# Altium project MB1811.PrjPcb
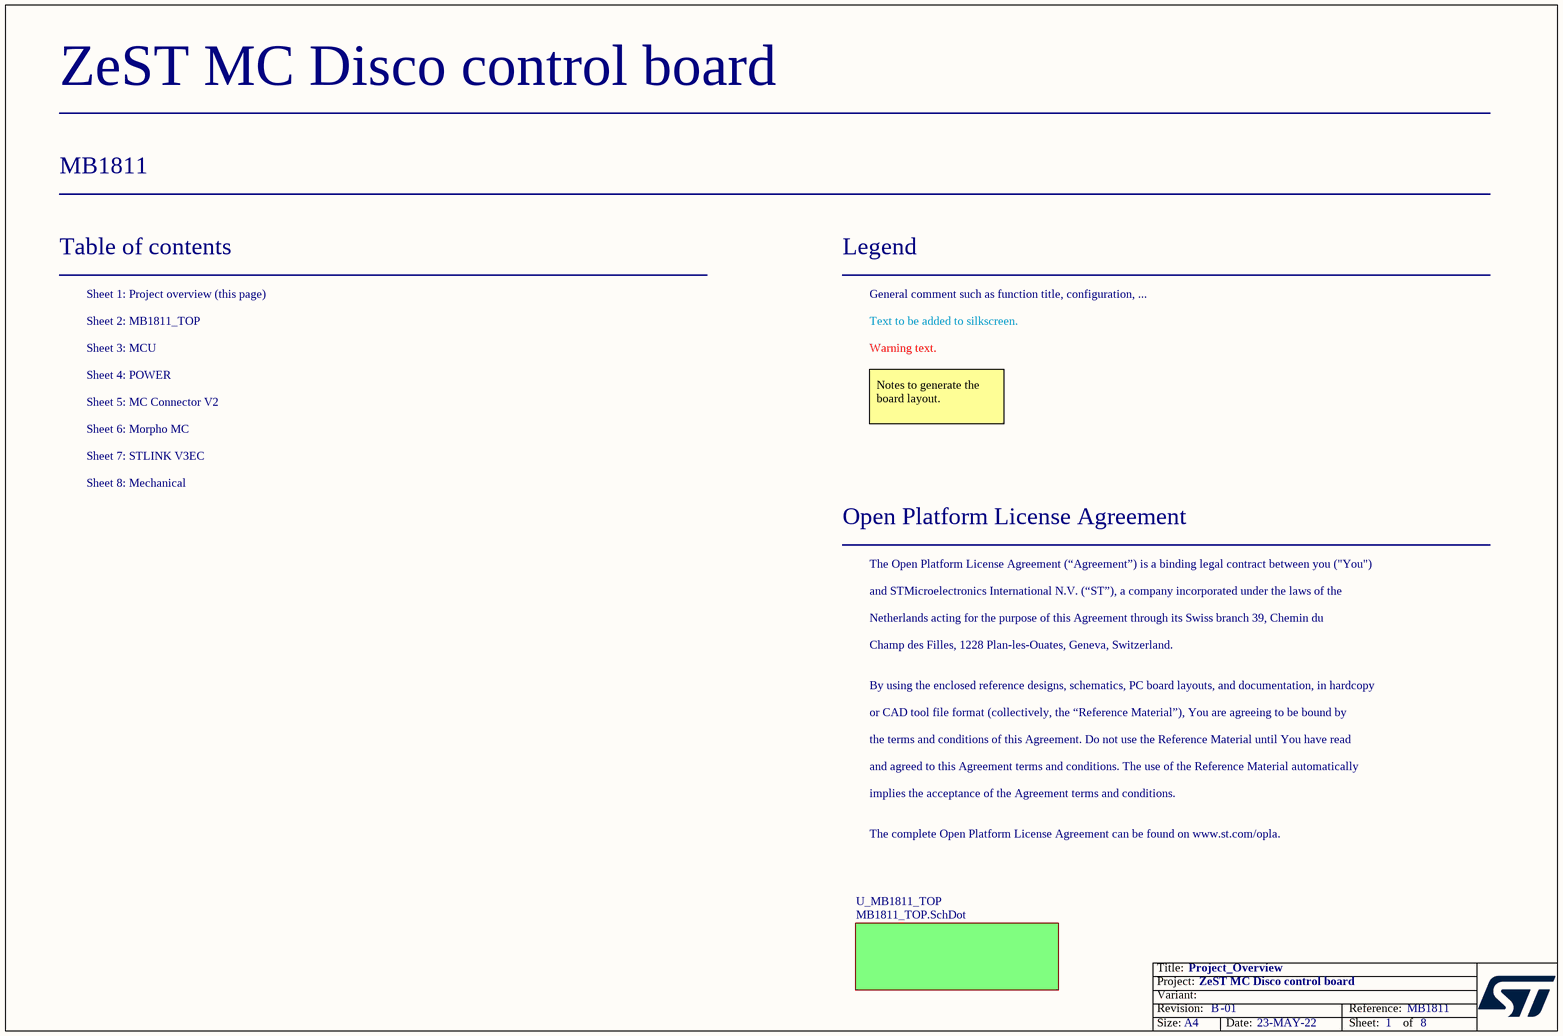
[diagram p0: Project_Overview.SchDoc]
Board_Assembly_Revision: 01; Board_Document_Date: 23-MAY-22; Board_Name: ZeST MC Disco control board; Board_PCB_Revision: B; Board_Reference: MB1811
2 sheets, 89 parts. Net scope: flat (ports and power ports of the same name join across sheets).
Board file: MB1811.PcbDoc
Sheets:
  Project_Overview.SchDoc
  STLINK_V3EC.SchDoc

## Sheet Project_Overview.SchDoc: Project_Overview
size A4; Date: Not used; ApprovedBy: Not used; CheckedBy: Not used; Author: Not used; CompanyName: STMicroelectronics; DrawnBy: Not used; Engineer: Not used; Organization: Not used; Address1: Not used; Address2: Not used; Address3: Not used; Address4: Not used; DocumentNumber: Not used; Revision: Not used; SheetNumber: 1; SheetTotal: 8

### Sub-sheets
U_MB1811_TOP = MB1811_TOP.SchDot (file not in this document): no entries

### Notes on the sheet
- Table of contents
- Sheet 1: Project overview (this page)
- Legend
- General comment such as function title, configuration, ...
- Sheet 2: MB1811_TOP
- Sheet 3: MCU
- Sheet 4: POWER
- Text to be added to silkscreen.
- Warning text.
- Sheet 6: Morpho MC
- Sheet 5: MC Connector V2
- Notes to generate the board layout.
- Sheet 7: STLINK V3EC
- Sheet 8: Mechanical
- Open Platform License Agreement
- The Open Platform License Agreement (“Agreement”) is a binding legal contract between you ("You")
- and STMicroelectronics International N.V. (“ST”), a company incorporated under the laws of the
- Netherlands acting for the purpose of this Agreement through its Swiss branch 39, Chemin du
- Champ des Filles, 1228 Plan-les-Ouates, Geneva, Switzerland.
- By using the enclosed reference designs, schematics, PC board layouts, and documentation, in hardcopy
- or CAD tool file format (collectively, the “Reference Material”), You are agreeing to be bound by
- the terms and conditions of this Agreement. Do not use the Reference Material until You have read
- and agreed to this Agreement terms and conditions. The use of the Reference Material automatically
- implies the acceptance of the Agreement terms and conditions.
- The complete Open Platform License Agreement can be found on www.st.com/opla.

## Sheet STLINK_V3EC.SchDoc: STLINK-V3EC
size A3; Date: Not used; ApprovedBy: Not used; CheckedBy: Not used; Author: Not used; CompanyName: STMicroelectronics; DrawnBy: Not used; Engineer: Not used; Organization: Not used; Address1: Not used; Address2: Not used; Address3: Not used; Address4: Not used; DocumentNumber: Not used; Revision: Not used; SheetNumber: 7; SheetTotal: 8
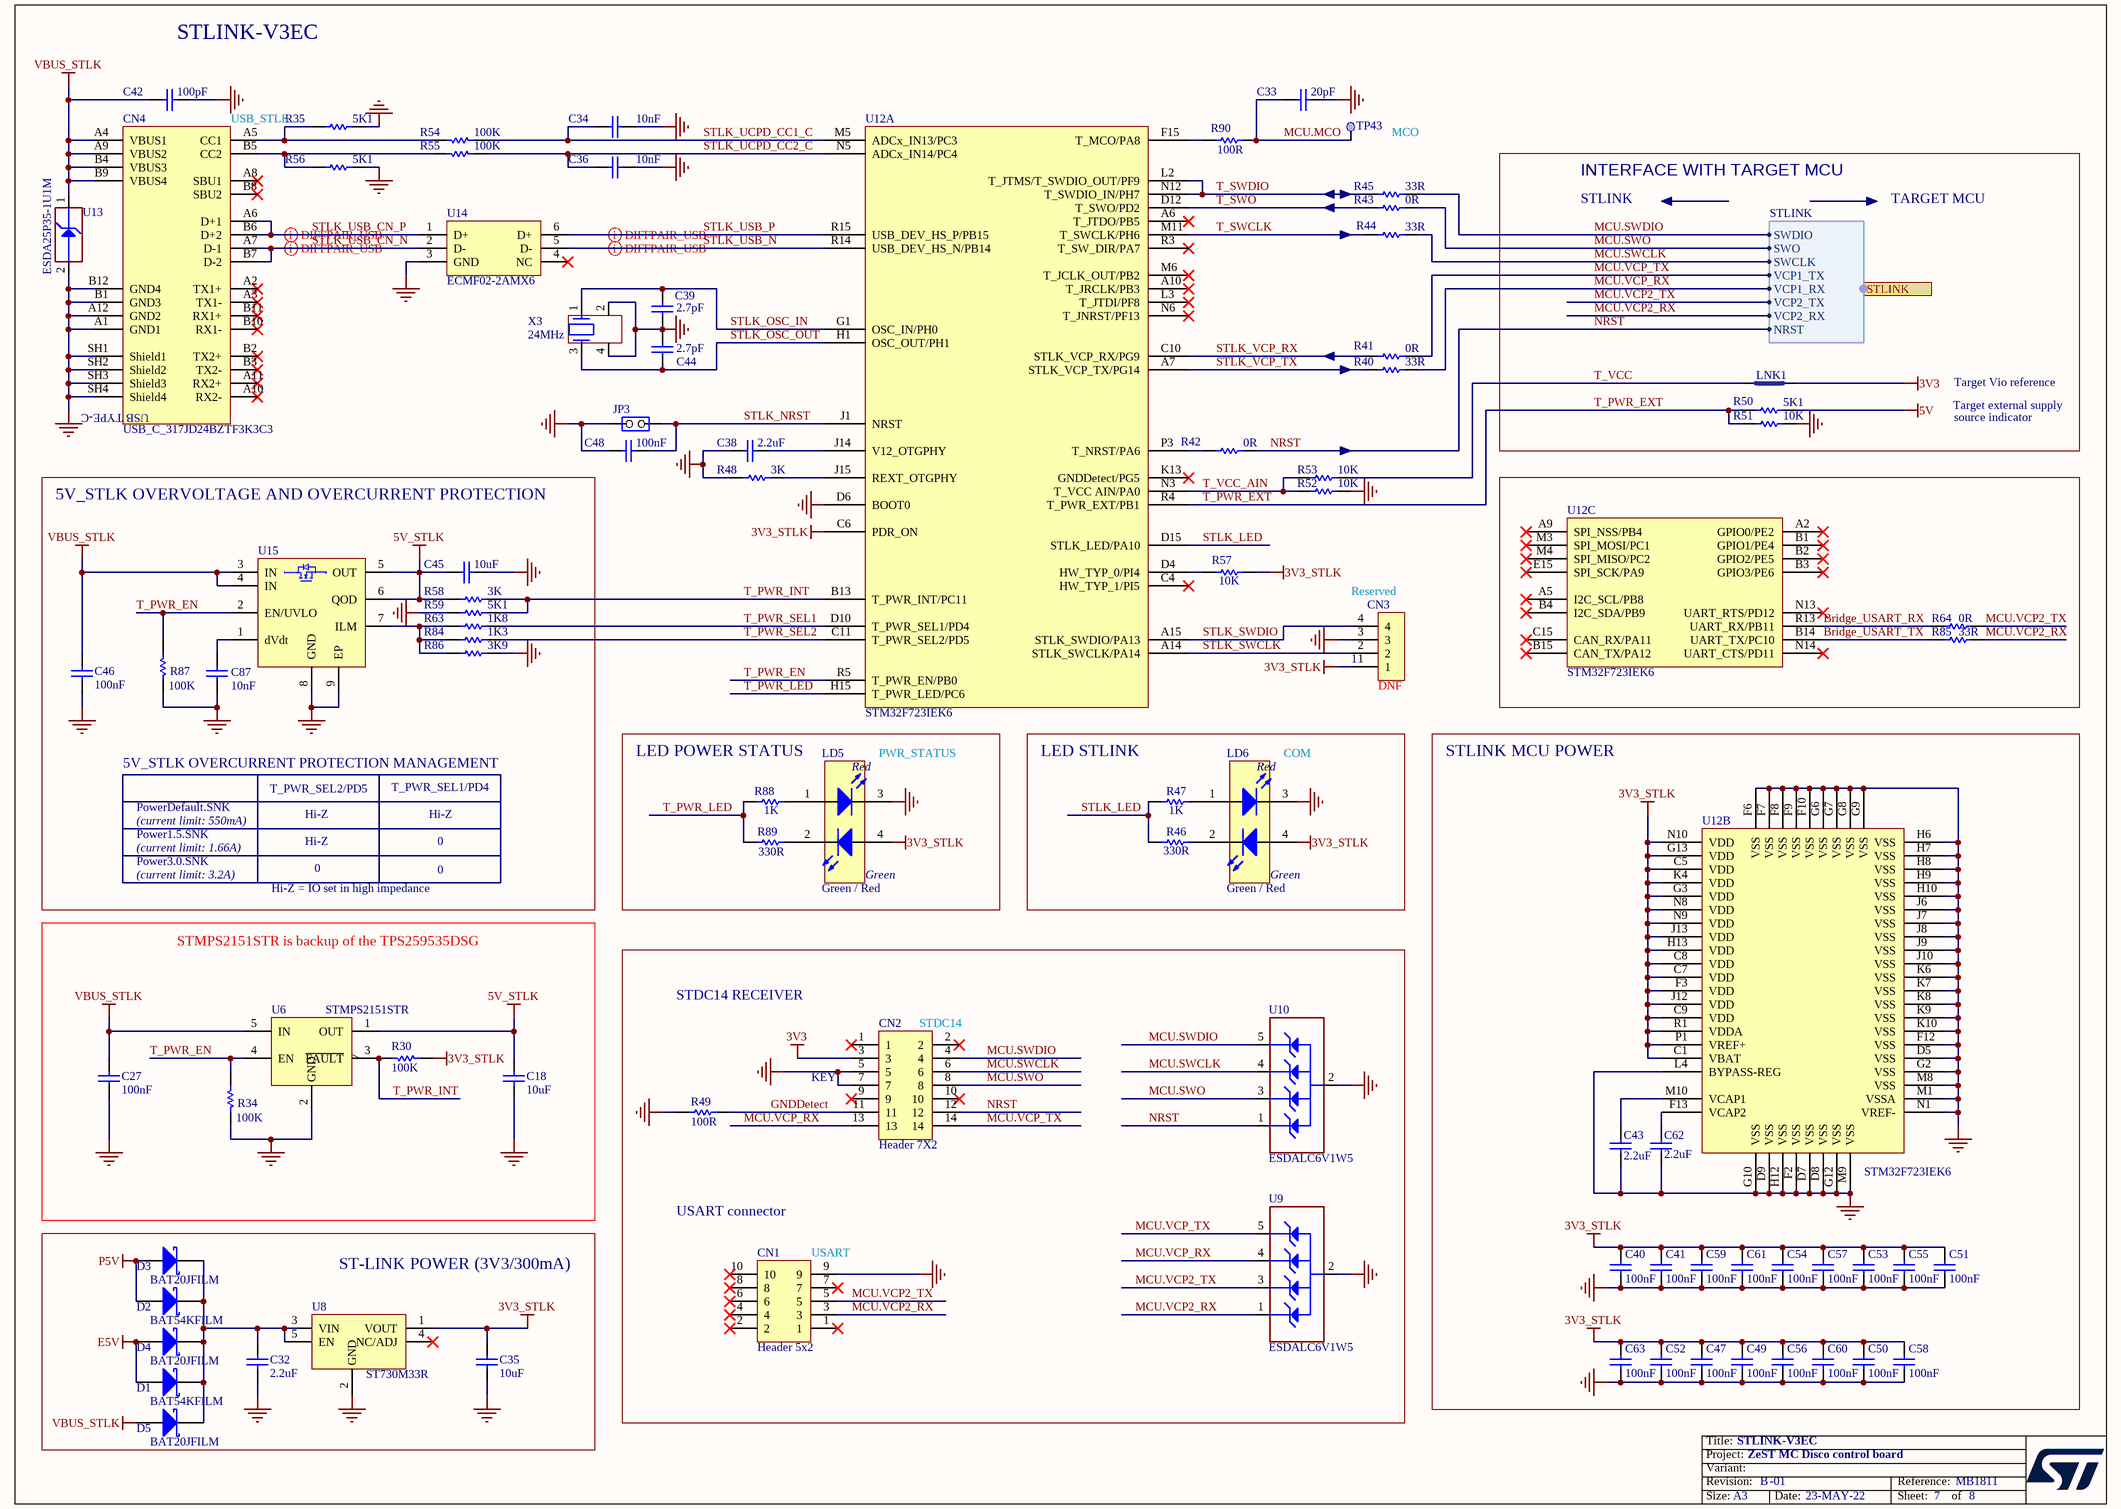
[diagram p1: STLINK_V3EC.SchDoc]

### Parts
C18  value 10uF  [C0603]  (hidden comment: Capacitor)
C27  value 100nF  [C0402]  (hidden comment: Capacitor)
C32  value 2.2uF  [C0805]  (hidden comment: Capacitor)
C33  value 20pF  [C0402]  (hidden comment: Capacitor)
C34  value 10nF  [C0402]  (hidden comment: Capacitor)
C35  value 10uF  [C0603]  (hidden comment: Capacitor)
C36  value 10nF  [C0402]  (hidden comment: Capacitor)
C38  value 2.2uF  [C0402]  (hidden comment: Capacitor)
C39  value 2.7pF  [C0402]  (hidden comment: Capacitor)
C40  value 100nF  [C0402]  (hidden comment: Capacitor)
C41  value 100nF  [C0402]  (hidden comment: Capacitor)
C42  value 100pF  [C0402]  (hidden comment: Capacitor)
C43  value 2.2uF  [C0402]  (hidden comment: Capacitor)
C44  value 2.7pF  [C0402]  (hidden comment: Capacitor)
C45  value 10uF  [C0603]  (hidden comment: Capacitor)
C46  value 100nF  [C0402]  (hidden comment: Capacitor)
C47  value 100nF  [C0402]  (hidden comment: Capacitor)
C48  value 100nF  [C0402]  (hidden comment: Capacitor)
C49  value 100nF  [C0402]  (hidden comment: Capacitor)
C50  value 100nF  [C0402]  (hidden comment: Capacitor)
C51  value 100nF  [C0402]  (hidden comment: Capacitor)
C52  value 100nF  [C0402]  (hidden comment: Capacitor)
C53  value 100nF  [C0402]  (hidden comment: Capacitor)
C54  value 100nF  [C0402]  (hidden comment: Capacitor)
C55  value 100nF  [C0402]  (hidden comment: Capacitor)
C56  value 100nF  [C0402]  (hidden comment: Capacitor)
C57  value 100nF  [C0402]  (hidden comment: Capacitor)
C58  value 100nF  [C0402]  (hidden comment: Capacitor)
C59  value 100nF  [C0402]  (hidden comment: Capacitor)
C60  value 100nF  [C0402]  (hidden comment: Capacitor)
C61  value 100nF  [C0402]  (hidden comment: Capacitor)
C62  value 2.2uF  [C0402]  (hidden comment: Capacitor)
C63  value 100nF  [C0402]  (hidden comment: Capacitor)
C87  value 10nF  [C0402]  (hidden comment: Capacitor)
CN1  Header 5x2  [CON_SAMTEC_FTSH-105-01-L-DV-K]
CN2  Header 7x2  [CON_SAMTEC_FTSH-107-01-L-DV-K-A]
CN3  Header 4x1  [CON_SAMTEC_TSW-104-07-G-S]  (value not drawn)
CN4  value USB_C_317JD24BZTF3K3C3  [CON_USB-TYPEC_COXOC_317JD24BZTF3K3C3]  (hidden comment: USB_TYPE_C_Receptacle_317JD24BZTF3K3C3)
D1  value BAT54KFILM  [DIO_SOD523_1A_2K]  (hidden comment: SCHOTTKY_1A_2K)
D2  value BAT54KFILM  [DIO_SOD523_1A_2K]  (hidden comment: SCHOTTKY_1A_2K)
D3  value BAT20JFILM  [DIO_SOD323_1A_2K]  (hidden comment: SCHOTTKY_1A_2K)
D4  value BAT20JFILM  [DIO_SOD323_1A_2K]  (hidden comment: SCHOTTKY_1A_2K)
D5  value BAT20JFILM  [DIO_SOD323_1A_2K]  (hidden comment: SCHOTTKY_1A_2K)
JP3  Jumper_Header 2x1  [CON_SAMTEC_TSW-102-07-G-S]  (value not drawn)
LD5  value Green / Red  [LED_BI-GR_WE-150141SV73110]  (hidden comment: LED_BICOLOR)
LD6  value Green / Red  [LED_BI-GR_WE-150141SV73110]  (hidden comment: LED_BICOLOR)
LNK1  link_200  [LINK200]  (value not drawn)  (no BOM)
R30  value 100K  [R0402]  (hidden comment: Resistor)
R34  value 100K  [R0402]  (hidden comment: Resistor)
R35  value 5K1  [R0402]  (hidden comment: Resistor)
R40  value 33R  [R0402]  (hidden comment: Resistor)
R41  value 0R  [R0402]  (hidden comment: Resistor)
R42  value 0R  [R0402]  (hidden comment: Resistor)
R43  value 0R  [R0402]  (hidden comment: Resistor)
R44  value 33R  [R0402]  (hidden comment: Resistor)
R45  value 33R  [R0402]  (hidden comment: Resistor)
R46  value 330R  [R0402]  (hidden comment: Resistor)
R47  value 1K  [R0402]  (hidden comment: Resistor)
R48  value 3K  [R0402]  (hidden comment: Resistor)
R49  value 100R  [R0402]  (hidden comment: Resistor)
R50  value 5K1  [R0402]  (hidden comment: Resistor)
R51  value 10K  [R0402]  (hidden comment: Resistor)
R52  value 10K  [R0402]  (hidden comment: Resistor)
R53  value 10K  [R0402]  (hidden comment: Resistor)
R54  value 100K  [R0402]  (hidden comment: Resistor)
R55  value 100K  [R0402]  (hidden comment: Resistor)
R56  value 5K1  [R0402]  (hidden comment: Resistor)
R57  value 10K  [R0402]  (hidden comment: Resistor)
R58  value 3K  [R0402]  (hidden comment: Resistor)
R59  value 5K1  [R0402]  (hidden comment: Resistor)
R63  value 1K8  [R0402]  (hidden comment: Resistor)
R64  value 0R  [R0402]  (hidden comment: Resistor)
R84  value 1K3  [R0402]  (hidden comment: Resistor)
R85  value 33R  [R0402]  (hidden comment: Resistor)
R86  value 3K9  [R0402]  (hidden comment: Resistor)
R87  value 100K  [R0402]  (hidden comment: Resistor)
R88  value 1K  [R0402]  (hidden comment: Resistor)
R89  value 330R  [R0402]  (hidden comment: Resistor)
R90  value 100R  [R0402]  (hidden comment: Resistor)
TP43  Test Point  [TP_SMD_1MM]  (value not drawn)  (no BOM)
U6  STMPS2151STR  [MOS_SOT23-5L]
U8  ST730M33R  [ICC_SOT23-5L_H1P45]
U9  ESDALC6V1W5  [ESD_SOT323-5L]
U10  ESDALC6V1W5  [ESD_SOT323-5L]
U12  value STM32F723IEK6  [ICC_UFBGA201_176+25_10X10_P065]  (hidden comment: STLINK-V3EC)  (parts A,B,C of 3)
U13  value ESDA25P35-1U1M  [ESD_QFN1610_2N_1K_2A]  (hidden comment: ESD-TRANSIL)
U14  ECMF02-2AMX6  [ESD_QFN-6L_1P7X1P5_P050]
U15  TPS259535DSG  [ICC_WSON8-EPAD_2X2_P050]  (value not drawn)
X3  value 24MHz  [CRY_NX2016SA_4P]  (hidden comment: XTAL_4_PINS)

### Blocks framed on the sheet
INTERFACE WITH TARGET MCU: LNK1 R50 R51
5V_STLK OVERVOLTAGE AND OVERCURRENT PROTECTION: C45 C46 C87 R58 R59 R63 R84 R86 R87 U15
LED POWER STATUS: LD5 R88 R89
LED STLINK: LD6 R46 R47
STLINK MCU POWER: C40 C41 C43 C47 C49-C63 U12
STMPS2151STR is backup of the TPS259535DSG: C18 C27 R30 R34 U6
ST-LINK POWER (3V3/300mA): C32 C35 D1-D5 U8

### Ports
STLINK (harness STLINK)

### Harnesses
STLINK: SWDIO, SWO, VCP1_TX, SWCLK, VCP1_RX, VCP2_TX, VCP2_RX, NRST

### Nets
3V3: CN2.3 LNK1.1
3V3_STLK: C35.2 C40.1 C41.1 C47.1 C49.1 C50.1 C51.1 C52.1 C53.1 C54.1 C55.1 C56.1 C57.1 C58.1 C59.1 C60.1 C61.1 C63.1 CN3.1 LD5.4(Green_anode) LD6.4(Green_anode) R30.1 R57.2 U8.1(VOUT) U12.C1(VBAT) U12.C5(VDD) U12.C6(PDR_ON) U12.C7(VDD) U12.C8(VDD) U12.C9(VDD) U12.F3(VDD) U12.G3(VDD) U12.G13(VDD) U12.H13(VDD) U12.J12(VDD) U12.J13(VDD) U12.K4(VDD) U12.N8(VDD) U12.N9(VDD) U12.N10(VDD) U12.P1(VREF+) U12.R1(VDDA)
5V: R50.2
5V_STLK: C18.2 C45.2 R58.1 U6.1(OUT) U15.5(OUT) U15.6(QOD)
E5V: D1.1(A) D4.1(A)
GND: C18.1 C27.1 C32.1 C33.1 C34.2 C35.1 C36.2 C38.1 C39.2 C40.2 C41.2 C42.2 C43.1 C44.1 C45.1 C46.1 C47.2 C48.1 C49.2 C50.2 C51.2 C52.2 C53.2 C54.2 C55.2 C56.2 C57.2 C58.2 C59.2 C60.2 C61.2 C62.1 C63.2 C87.1 CN1.9 CN2.5 CN2.7 CN3.3 CN4.A1(GND1) CN4.A12(GND2) CN4.B1(GND3) CN4.B12(GND4) CN4.SH1(Shield1) CN4.SH2(Shield2) CN4.SH3(Shield3) CN4.SH4(Shield4) JP3.2(NO) LD5.3(RED_cathode) LD6.3(RED_cathode) R34.1 R35.2 R48.2 R49.1 R51.2 R52.2 R56.2 R59.2 R86.2 R87.1 U6.2(GND) U8.2(GND) U9.2(GND) U10.2(GND) U12.D5(VSS) U12.D6(BOOT0) U12.D7(VSS) U12.D8(VSS) U12.D9(VSS) U12.F2(VSS) U12.F6(VSS) U12.F7(VSS) U12.F8(VSS) U12.F9(VSS) U12.F10(VSS) U12.F12(VSS) U12.G2(VSS) U12.G6(VSS) U12.G7(VSS) U12.G8(VSS) U12.G9(VSS) U12.G10(VSS) U12.G12(VSS) U12.H6(VSS) U12.H7(VSS) U12.H8(VSS) U12.H9(VSS) U12.H10(VSS) U12.H12(VSS) U12.J6(VSS) U12.J7(VSS) U12.J8(VSS) U12.J9(VSS) U12.J10(VSS) U12.K6(VSS) U12.K7(VSS) U12.K8(VSS) U12.K9(VSS) U12.K10(VSS) U12.L4(BYPASS-REG) U12.M1(VSSA) U12.M8(VSS) U12.M9(VSS) U12.N1(VREF-) U13.2(GND) U14.3(GND) U15.8(GND) U15.9(EP) X3.2 X3.4
P5V: D2.1(A) D3.1(A)
VBUS_STLK: C27.2 C42.1 C46.2 CN4.A4(VBUS1) CN4.A9(VBUS2) CN4.B4(VBUS3) CN4.B9(VBUS4) D5.1(A) U6.5(IN) U13.1(IO1) U15.3(IN) U15.4(IN)
Bridge_USART_RX: R64.1 U12.R13(UART_RX/PB11)
Bridge_USART_TX: R85.1 U12.B14(UART_TX/PC10)
GNDDetect: CN2.11 R49.2
MCU.MCO: C33.2 R90.2 TP43.1
MCU.SWCLK: CN2.6 R44.2 U10.4(IO3) ; port STLINK.SWCLK
MCU.SWDIO: CN2.4 R45.2 U10.5(IO4) ; port STLINK.SWDIO
MCU.SWO: CN2.8 R43.2 U10.3(IO2) ; port STLINK.SWO
MCU.VCP2_RX: CN1.3 R85.2 U9.1(IO1) ; port STLINK.VCP2_RX
MCU.VCP2_TX: CN1.5 R64.2 U9.3(IO2) ; port STLINK.VCP2_TX
MCU.VCP_RX: CN2.13 R40.2 U9.4(IO3) ; port STLINK.VCP1_RX
MCU.VCP_TX: CN2.14 R41.2 U9.5(IO4) ; port STLINK.VCP1_TX
NRST: CN2.12 R42.2 U10.1(IO1) ; port STLINK.NRST
STLK_LED: R46.1 R47.2 U12.D15(STLK_LED/PA10)
STLK_NRST: C48.2 JP3.1(COMMON) U12.J1(NRST)
STLK_OSC_IN: C39.1 U12.G1(OSC_IN/PH0) X3.1
STLK_OSC_OUT: C44.2 U12.H1(OSC_OUT/PH1) X3.3
STLK_SWCLK: CN3.2 U12.A14(STLK_SWCLK/PA14)
STLK_SWDIO: CN3.4 U12.A15(STLK_SWDIO/PA13)
STLK_UCPD_CC1_C: C34.1 R54.1 U12.M5(ADCx_IN13/PC3)
STLK_UCPD_CC2_C: C36.1 R55.1 U12.N5(ADCx_IN14/PC4)
STLK_USB_CN_N: CN4.A7(D-1) CN4.B7(D-2) U14.2(D-)
STLK_USB_CN_P: CN4.A6(D+1) CN4.B6(D+2) U14.1(D+)
STLK_USB_N: U12.R14(USB_DEV_HS_N/PB14) U14.5(D-)
STLK_USB_P: U12.R15(USB_DEV_HS_P/PB15) U14.6(D+)
STLK_VCP_RX: R41.1 U12.C10(STLK_VCP_RX/PG9)
STLK_VCP_TX: R40.1 U12.A7(STLK_VCP_TX/PG14)
T_PWR_EN: R34.2 R87.2 U6.4(EN) U12.R5(T_PWR_EN/PB0) U15.2(EN/UVLO)
T_PWR_EXT: R50.1 R51.1 U12.R4(T_PWR_EXT/PB1)
T_PWR_INT: R30.2 R58.2 R59.1 U6.3(~{FAULT}) U12.B13(T_PWR_INT/PC11)
T_PWR_LED: R88.2 R89.2 U12.H15(T_PWR_LED/PC6)
T_PWR_SEL1: R63.2 U12.D10(T_PWR_SEL1/PD4)
T_PWR_SEL2: R84.2 U12.C11(T_PWR_SEL2/PD5)
T_SWCLK: R44.1 U12.M11(T_SWCLK/PH6)
T_SWDIO: R45.1 U12.L2(T_JTMS/T_SWDIO_OUT/PF9) U12.N12(T_SWDIO_IN/PH7)
T_SWO: R43.1 U12.D12(T_SWO/PD2)
T_VCC: LNK1.2 R53.2
T_VCC_AIN: R52.1 R53.1 U12.N3(T_VCC_AIN/PA0)
NetC32_2: C32.2 D1.2(K) D2.2(K) D3.2(K) D4.2(K) D5.2(K) U8.3(VIN) U8.5(EN)
NetC38_2: C38.2 U12.J14(V12_OTGPHY)
NetC43_2: C43.2 U12.M10(VCAP1)
NetC62_2: C62.2 U12.F13(VCAP2)
NetC87_2: C87.2 U15.1(dVdt)
NetCN4_A5: CN4.A5(CC1) R35.1 R54.2
NetCN4_B5: CN4.B5(CC2) R55.2 R56.1
NetLD5_1: LD5.1(Red_anode) R88.1
NetLD5_2: LD5.2(Green_cathode) R89.1
NetLD6_1: LD6.1(Red_anode) R47.1
NetLD6_2: LD6.2(Green_cathode) R46.2
NetR42_1: R42.1 U12.P3(T_NRST/PA6)
NetR48_1: R48.1 U12.J15(REXT_OTGPHY)
NetR57_1: R57.1 U12.D4(HW_TYP_0/PI4)
NetR63_1: R63.1 R84.1 R86.1 U15.7(ILM)
NetR90_1: R90.1 U12.F15(T_MCO/PA8)

Not connected (* = marked no-connect by the designer): CN1 1* 2* 4* 6* 7* 8* 10*; CN2 1* 2* 9* 10*; CN4 A2(TX1+)* A3(TX1-)* A8(SBU1)* A10(RX2-)* A11(RX2+)* B2(TX2+)* B3(TX2-)* B8(SBU2)* B10(RX1-)* B11(RX1+)*; U8 4(NC/ADJ)*; U12 A2(GPIO0/PE2)* A5(I2C_SCL/PB8)* A6(T_JTDO/PB5)* A9(SPI_NSS/PB4)* A10(T_JRCLK/PB3)* B1(GPIO1/PE4)* B2(GPIO2/PE5)* B3(GPIO3/PE6)* B4(I2C_SDA/PB9)* B15(CAN_TX/PA12)* C4(HW_TYP_1/PI5)* C15(CAN_RX/PA11)* E15(SPI_SCK/PA9)* K13(GNDDetect/PG5)* L3(T_JTDI/PF8)* M3(SPI_MOSI/PC1)* M4(SPI_MISO/PC2)* M6(T_JCLK_OUT/PB2)* N6(T_JNRST/PF13)* N13(UART_RTS/PD12)* N14(UART_CTS/PD11)* R3(T_SW_DIR/PA7)*; U14 4(NC)*

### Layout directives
differential pair; rule Impedance Constraint [Min = 85.00    Max = 95.00    ]: STLK_USB_CN_N, STLK_USB_CN_P, STLK_USB_N, STLK_USB_P

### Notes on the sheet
- STLINK-V3EC
- USB_STLK
- MCO
- STLINK
- TARGET MCU
- Target external supply
- Target Vio reference
- source indicator
- (near CN3) Reserved
- (near CN3) 1
- (near CN3) DNF
- 5V_STLK OVERCURRENT PROTECTION MANAGEMENT
- PWR_STATUS
- (near LD6) COM
- (current limit: 550mA)
- (current limit: 1.66A)
- Power1.5.SNK
- PowerDefault.SNK
- T_PWR_SEL2/PD5
- Hi-Z
- T_PWR_SEL1/PD4
- 0
- (current limit: 3.2A)
- Power3.0.SNK
- Hi-Z = IO set in high impedance
- STDC14 RECEIVER
- (near CN2) STDC14
- (near CN2) KEY
- USART connector
- (near CN1) USART

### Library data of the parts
C18 C35 C45 = MCD-00099: Capacitor, MLCC, 10uF, 10V, X5R, +/-10%, 0603, T=0.8mm; Part_Preference: Recommended; Manufacturer: MURATA; Manufacturer_Part_Number: GRM188R61A106KE69D; Order_Code_RS: 170-6168; Component_Country_Of_Origin: Japan; ShowFields: YES; ID: 2770
C27 C46 = MCD-02355: Capacitor, MLCC, 100nF, 25V, X7R, +/-10%, 0402, T=0.5mm; Part_Preference: Recommended; Manufacturer: WALSIN; Manufacturer_Part_Number: 0402B104K250CT; Order_Code_RS: 176-3114; Component_Country_Of_Origin: Unknown; ShowFields: YES; ID: 4461
C32 = MCD-02372: Capacitor, MLCC, 2.2uF, 25V, X7R, +/-10%, 0805, T=1,25mm; Manufacturer_Part_Number: GRM21BR71E225KE11L; Manufacturer: MURATA; Part_Preference: Recommended; Component_Country_Of_Origin: Japan; ShowFields: YES; ID: 4478
C33 = MCD-00016: Capacitor, MLCC, 20pF, 50V, NPO, +/- 5%, 0402, T=0.5mm; Manufacturer_Part_Number: CC0402JRNPO9BN200; Manufacturer: YAGEO; Part_Preference: Recommended; Component_Country_Of_Origin: China; ShowFields: YES; ID: 2479
C34 C36 C87 = MCD-02198: Capacitor, MLCC, 10nF, 50V, X7R, +/-10%, 0402, T=0.5mm; Part_Preference: Recommended; Manufacturer: YAGEO; Manufacturer_Part_Number: CC0402KRX7R9BB103; Order_Code_RS: 6169644; Component_Country_Of_Origin: China; ShowFields: YES; ID: 4298
C38 C43 C62 = MCD-02606: Capacitor, MLCC, 2.2uF, 6.3V, X5R, +/-10%, 0402, T=0.5mm; Part_Preference: Recommended; Manufacturer: YAGEO; Manufacturer_Part_Number: CC0402KRX5R5BB225; Order_Code_RS: 1992205; ShowFields: YES; ID: 4712
C39 C44 = MCD-01774: Capacitor, MLCC, 2.7pF, 50V, NPO, +/-0.1pF, 0402, T=0.5mm; Part_Preference: Recommended; Manufacturer: YAGEO; Manufacturer_Part_Number: CC0402BRNPO9BN2R7; Component_Country_Of_Origin: China; ShowFields: YES; ID: 3874
C40 C41 C47-C61 C63 = MCD-00006: Capacitor, MLCC, 100nF, 16V, X7R, +/-10%, 0402, T=0.5mm; Manufacturer_Part_Number: CC0402KRX7R7BB104; Manufacturer: YAGEO; Part_Preference: Recommended; Order_Code_RS: 616-9701; Component_Country_Of_Origin: China; ShowFields: YES; ID: 2474
C42 = MCD-00205: Capacitor, MLCC, 100pF, 50V, NPO, +/-5%, 0402, T=0.5mm; Part_Preference: Recommended; Manufacturer: YAGEO; Manufacturer_Part_Number: CC0402JRNPO9BN101; Component_Country_Of_Origin: China; ShowFields: YES; ID: 2658
CN1 = MCD-01951: Header, 5x2, 1.27mm, VR, SMD, T=5.97mm; Part_Type: Connector; Part_Preference: Recommended; Manufacturer: SAMTEC; Manufacturer_Part_Number: FTSH-105-01-L-DV-K-A; Order_Code_RS: 159-2343; Component_Country_Of_Origin: China, Costa Rica, Malaysia, United States, Vietnam; ShowFields: YES; ID: 4051
CN2 = MCD-01959: Header, 7x2, 1.27mm, VR, SMD, T=5.97mm; Part_Type: Connector; Part_Preference: Recommended; Manufacturer: SAMTEC; Manufacturer_Part_Number: FTSH-107-01-L-DV-K-A; Order_Code_RS: 208-1478; Component_Country_Of_Origin: China, Costa Rica, Malaysia, United States, Vietnam; ShowFields: YES; ID: 4059
CN3 = MCD-00029: Header, 4x1, 2.54mm, VR, TH, T=5.84mm/2.54mm; Manufacturer_Part_Number: TSW-104-07-G-S; Manufacturer: SAMTEC; Part_Type: Connector; Part_Preference: Recommended; Order_Code_RS: 161-2261; Component_Country_Of_Origin: China, Costa Rica, Malaysia, United States, Vietnam; ShowFields: YES; ID: 2487
CN4 = MCD-01108: USB_TypeC, SMD+DIP, T= 2.96mm (for 1.6mm pcb); Part_Type: Connector; Part_Preference: Recommended; Manufacturer: CHANT SINCERE (COXOC); Alternate_Manufacturer: Wurth; Alternate_Manufacturer_Part_Number: 632723300011
D1 D2 = MCD-01677: Small signal Schottky diodes; BMS_Part_Number: 9151123; Part_Type: Diode; Part_Preference: Recommended; Manufacturer: STMICROELECTRONICS; Manufacturer_HQ_COO: EU; Component_Country_Of_Origin: China; ShowFields: YES; ID: 3777
D3-D5 = MCD-03011: Diode, Signal Schottky, If=1A, Ifsm=5A, Vf =0.54V@1A, Vrrm=23V, Ir = 0.65µA@5V, SOD-323; Part_Preference: Recommended; Manufacturer: STMICROELECTRONICS; Order_Code_RS: 165-7545; ShowFields: YES; ID: 5127; Component_Country_Of_Origin: China
JP3 = MCD-00045: Header, 2x1, 2.54mm, VR, TH, T=5.84mm/2.54mm; Part_Preference: Recommended; Part_Type: Connector; Manufacturer: SAMTEC; Manufacturer_Part_Number: TSW-102-07-G-S; Full_Alternate_Internal_Part_Number: MCD-02390; Order_Code_RS: 155-5312; Component_Country_Of_Origin: China, Costa Rica, Malaysia, United States, Vietnam; ShowFields: YES; ID: 2545
LD5 LD6 = MCD-02631: LED Bicolor, Green/Red, 2V, 20mA,  4-PLCC; Part_Type: Display; Part_Preference: Recommended; Manufacturer: WURTH ELEKTRONIK; Manufacturer_Part_Number: 150141SV73110; Order_Code_RS: 184-6963; Component_Country_Of_Origin: China; ShowFields: YES; ID: 4737
LNK1 = MCD-02777: Track link on PCB 200um width for layout routing.; Part_Type: Misc; Part_Preference: Recommended; ShowFields: YES; ID: 4889
R30 R34 R54 R55 R87 = MCD-00059: Resistor, 100K, 0402, +/-1%, 1/16W; Manufacturer_Part_Number: RC0402FR-07100KL; Manufacturer: YAGEO; Part_Preference: Recommended; Component_Country_Of_Origin: China; ShowFields: YES; ID: 2533
R35 R50 R56 R59 = MCD-00333: Resistor, 5K1, 0402, +/-1%, 1/16W; Part_Preference: Recommended; Manufacturer: YAGEO; Manufacturer_Part_Number: RC0402FR-075K1L; Component_Country_Of_Origin: China; ShowFields: YES; ID: 2944
R40 R44 R45 R85 = MCD-00455: Resistor, 33R, 0402, +/-1%, 1/16W; Part_Preference: Recommended; Manufacturer: YAGEO; Manufacturer_Part_Number: RC0402FR-0733RL; Component_Country_Of_Origin: China; ShowFields: YES; ID: 2821
R41-R43 R64 = MCD-00052: Resistor, 0R, 0402, +/-5%, 1/16W; Part_Preference: Recommended; Manufacturer: YAGEO; Manufacturer_Part_Number: RC0402JR-070RL; Order_Code_RS: 618-5804; Component_Country_Of_Origin: China; ShowFields: YES; ID: 2540
R46 R89 = MCD-00062: Resistor, 330R, 0402, +/-1%, 1/16W; Part_Preference: Recommended; Manufacturer: YAGEO; Manufacturer_Part_Number: RC0402FR-07330RL; Component_Country_Of_Origin: China; ShowFields: YES; ID: 2529
R47 R88 = MCD-02665: Resistor, 1K, 0402, +/-0.1%, 1/16W, +/-25ppm/°C; Part_Preference: Recommended; Manufacturer: YAGEO; Manufacturer_Part_Number: RT0402BRD071KL; Order_Code_RS: 199-1298; ShowFields: YES; ID: 4771
R48 = MCD-00185: Resistor, 3K, 0402, +/-1%, 1/16W; Manufacturer_Part_Number: RC0402FR-073KL; Manufacturer: YAGEO; Part_Preference: Recommended; Component_Country_Of_Origin: China; ShowFields: YES; ID: 2682
R49 R90 = MCD-00067: Resistor, 100R, 0402, +/- 1%, 1/16W; Part_Preference: Recommended; Manufacturer: YAGEO; Manufacturer_Part_Number: RC0402FR-07100RL; Component_Country_Of_Origin: China; ShowFields: YES; ID: 2527
R51-R53 R57 = MCD-00053: Resistor, 10K, 0402, +/-1%, 1/16W; Manufacturer_Part_Number: RC0402FR-0710KL; Manufacturer: YAGEO; BMS_Part_Number: 9131590; Part_Preference: Recommended; Component_Country_Of_Origin: China; ShowFields: YES; ID: 2539
R58 = MCD-00185: Resistor, 3K, 0402, +/-1%, 1/16W; Part_Preference: Recommended; Manufacturer: YAGEO; Manufacturer_Part_Number: RC0402FR-073KL; Component_Country_Of_Origin: China; ShowFields: YES; ID: 2682
R63 = MCD-00409: Resistor, 1K8, 0402, +/-1%, 1/16W; Part_Preference: Recommended; Manufacturer: YAGEO; Manufacturer_Part_Number: RC0402FR-071K8L; Component_Country_Of_Origin: China; ShowFields: YES; ID: 2871
R84 = MCD-00381: Resistor, 1K3, 0402, +/-1%, 1/16W; Part_Preference: Recommended; Manufacturer: YAGEO; Manufacturer_Part_Number: RC0402FR-071K3L; Component_Country_Of_Origin: China; ShowFields: YES; ID: 2898
R86 = MCD-02455: Resistor, 3K9, 0402, +/-1%, 1/16W, +/-100ppm/°C; Part_Preference: Recommended; Manufacturer: YAGEO; Manufacturer_Part_Number: RC0402FR-073K9L; Order_Code_RS: 198-7783; Component_Country_Of_Origin: China; ShowFields: YES; ID: 4561
TP43 = MCD-00074: Test Point 1mm; Part_Type: Misc; Part_Preference: Recommended; ShowFields: YES; ID: 2518
U6 = MCD-00159: 500mA, Enhanced single channel power switches with active high enable pin; Part_Type: IC; Manufacturer: STMICROELECTRONICS; BMS_Part_Number: 9159009; Part_Preference: Recommended; Manufacturer_HQ_COO: EU; Order_Code_RS: 880-5415; Component_Country_Of_Origin: Malaysia; ShowFields: YES; ID: 2708
U8 = MCD-02514: LDO, 3.3V, 300mA, High input voltage: 2.5V to 28V, SOT23-5L; Part_Type: IC; Part_Preference: Recommended; Manufacturer: STMICROELECTRONICS; Component_Country_Of_Origin: Malaysia; ShowFields: YES; ID: 4620
U9 U10 = MCD-00136: Dual Transil array for ESD protection; BMS_Part_Number: 9151112; Part_Type: Diode; Part_Preference: Recommended; Manufacturer: STMICROELECTRONICS; Manufacturer_HQ_COO: EU; Component_Country_Of_Origin: China; ShowFields: YES; ID: 2731
U12 = MCD-02706: MCU, Arm Cortex-M7 32-bit MCU, 512KB Flash, 276KB RAM, With Crypto; BMS_Part_Number: 9175300; Part_Type: IC; Part_Preference: Recommended; Manufacturer: STMICROELECTRONICS; Order_Code_RS: 135-8241; ShowFields: YES; ID: 4812
U13 = MCD-01207: High power Transient voltage suppressor:25V/35A EOS and ESD transients protection.; Part_Type: Diode; Manufacturer: STMICROELECTRONICS; BMS_Part_Number: 9179045; Part_Preference: Recommended; Manufacturer_HQ_COO: EU; Component_Country_Of_Origin: China; ShowFields: YES; ID: 3289
U14 = MCD-00649: Common mode filter with ESD protection for USB 2.0 interface; BMS_Part_Number: 9151138; Part_Type: Diode; Part_Preference: Recommended; Manufacturer: STMICROELECTRONICS; Manufacturer_HQ_COO: EU; Component_Country_Of_Origin: China; ShowFields: YES; ID: 3094
U15 = MCD-02532: IC, eFuse with Fast Overvoltage Protection 2.7V to 18V 4A 34mOhm 8-Pin WSON; Part_Preference: Recommended; Manufacturer: TEXAS INSTRUMENTS; ShowFields: YES; ID: 4638
X3 = MCD-01036: Crystal, 24MHz, 6pF, +/-20ppm, 80R, 2x1.6mm; BMS_Part_Number: 9157045; Part_Type: Crystal_Osc; Part_Preference: Recommended; Manufacturer: NDK; Manufacturer_Part_Number: NX2016SA-24MHZ-EXS00A-CS10820; Component_Country_Of_Origin: Unknown; ShowFields: YES; ID: 2989

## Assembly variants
G473QE: not fitted C11 C18 C27 C33 CN3 D1 D2 JP3 R30 R34 R49 R74 R76 R91 R92 R93 R94 R95 R96 R97 R98 R99 SB9 SB10 SB19 SB20 SB21 SB24 SB25 SB31 SB37 SB49 SB54 SB56 SB57 SB63 SB64 SB73 SB77 SB80 U6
